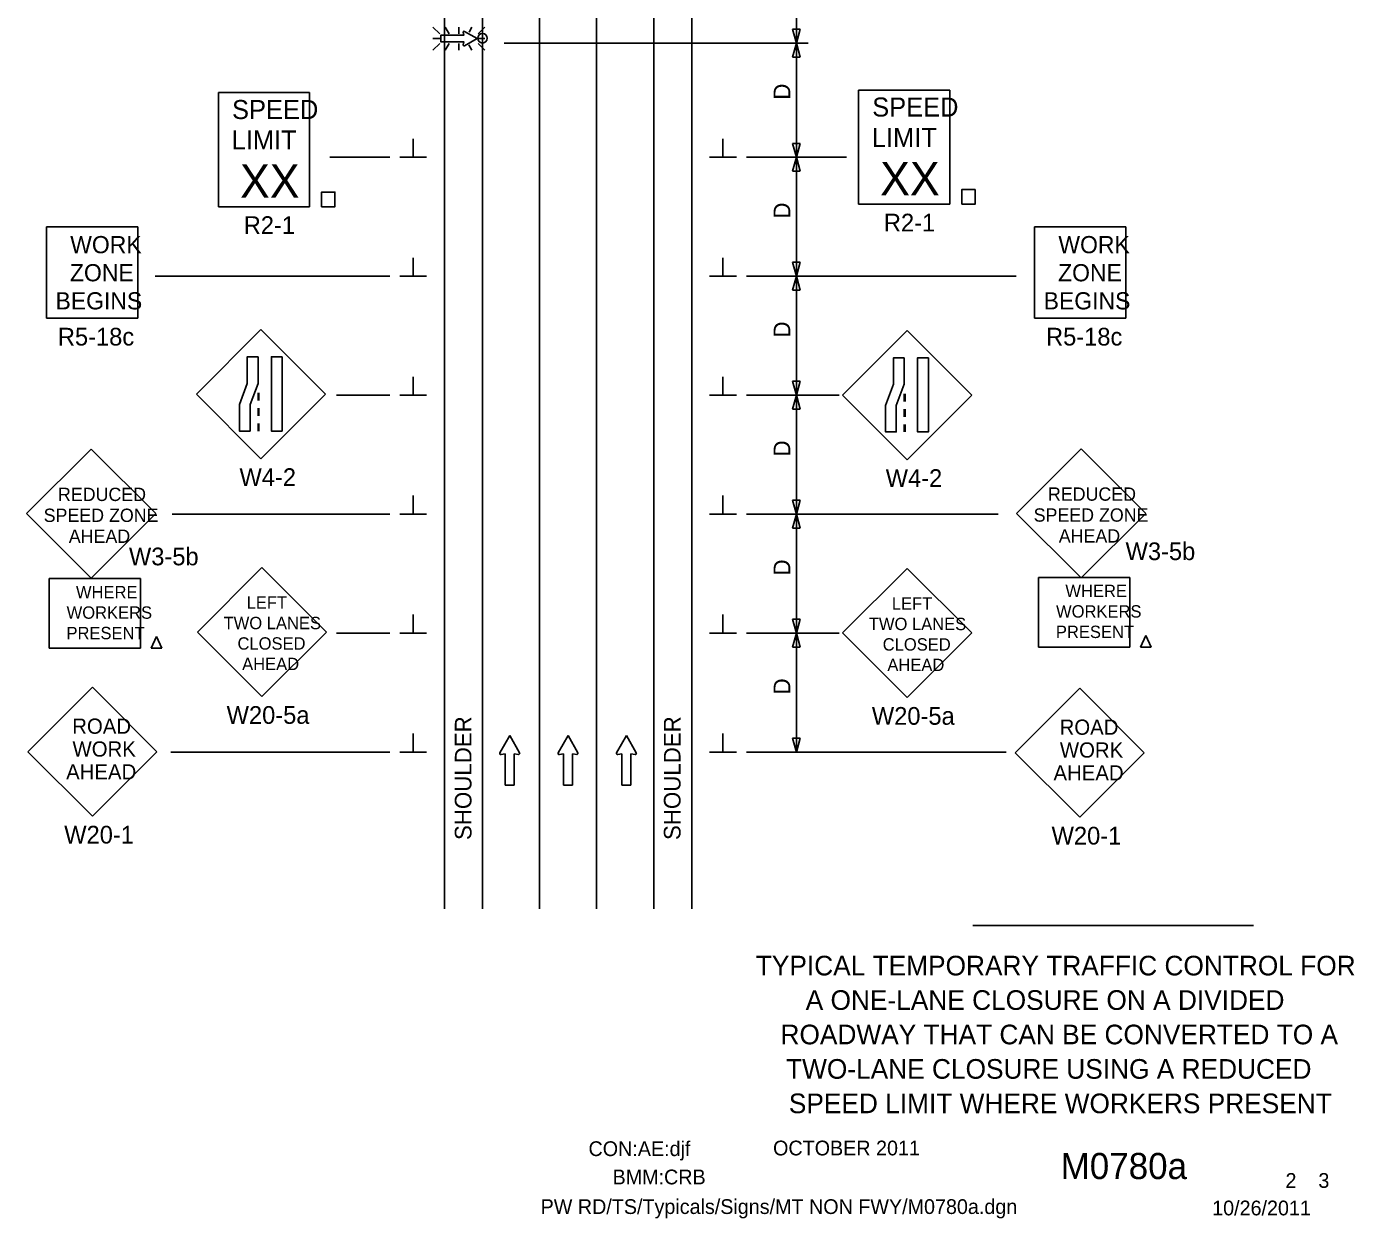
# Model space of a CAD drawing. Extents: x 16758 to 19504, y 5731 to 6944.
# Drawn here: x 17883 to 18442, y 5932 to 6433 of the extents above; entities that cross this region are included whole.
import ezdxf

# ---------------------------------------------------------------- set-up
doc = ezdxf.new("R2010")
doc.units = 0
for name, color, linetype in [('ALI_LEGAL_EX', 7, 'Continuous'), ('BORDER', 7, 'Continuous'), ('BORDER_SIGNAL_WO', 7, 'Continuous'), ('MT_SCRATCH_LEVEL_E', 7, 'Continuous'), ('PAVT_EDGE_EX', 7, 'Continuous'), ('TRAFFIC_SIGNS_PR', 7, 'Continuous'), ('TYPICAL_TEXT_DIMEN_PR', 7, 'Continuous')]:
    doc.layers.add(name, color=color, linetype=linetype)

msp = doc.modelspace()

# ---------------------------------------------------------------- linework, layer by layer
at = {"layer": 'ALI_LEGAL_EX'}
for p, q in [((18099.1, 6891.16), (18099.1, 6061.98)), ((18123.1, 6891.16), (18123.1, 6061.98)), ((18123.1, 6891.16), (18123.1, 6061.98))]:
    msp.add_line(p, q, dxfattribs=at)
for points in [[(18099.1, 6391.16), (18099.1, 6366.16)], [(18123.1, 6391.16), (18123.1, 6366.16)], [(18099.1, 6291.16), (18099.1, 6266.16)], [(18123.1, 6291.16), (18123.1, 6266.16)], [(18099.1, 6191.16), (18099.1, 6166.16)], [(18123.1, 6191.16), (18123.1, 6166.16)], [(18099.1, 6091.16), (18099.1, 6066.16)], [(18123.1, 6066.16), (18123.1, 6091.16)], [(18123.1, 6091.16), (18123.1, 6066.16)]]:
    msp.add_lwpolyline(points, dxfattribs=at)
at = {"layer": 'BORDER'}
for p, q in [((18281.35, 6055), (18399.35, 6055)), ((18318.25, 6011.25), (18318.25, 6011.25))]:
    msp.add_line(p, q, dxfattribs=at)
at = {"layer": 'MT_SCRATCH_LEVEL_E'}
for p, q in [((18086.54, 6134.8), (18082.43, 6127.56)), ((18086.54, 6134.8), (18082.43, 6127.56)), ((18090.69, 6127.56), (18086.54, 6134.8)), ((18090.69, 6127.56), (18086.54, 6134.8)), ((18111.07, 6134.8), (18106.96, 6127.56)), ((18111.07, 6134.8), (18106.96, 6127.56)), ((18115.21, 6127.56), (18111.07, 6134.8)), ((18115.21, 6127.56), (18111.07, 6134.8)), ((18135.63, 6134.8), (18131.52, 6127.56)), ((18135.63, 6134.8), (18131.52, 6127.56)), ((18139.77, 6127.56), (18135.63, 6134.8)), ((18139.77, 6127.56), (18135.63, 6134.8)), ((18082.91, 6126.88), (18084.69, 6127.19)), ((18082.91, 6126.88), (18084.69, 6127.19)), ((18084.69, 6127.19), (18084.69, 6113.93)), ((18084.69, 6127.19), (18084.69, 6113.93)), ((18088.43, 6113.93), (18088.43, 6127.19)), ((18088.43, 6127.19), (18090.21, 6126.88)), ((18088.43, 6113.93), (18088.43, 6127.19)), ((18088.43, 6127.19), (18090.21, 6126.88)), ((18107.44, 6126.88), (18109.22, 6127.19)), ((18107.44, 6126.88), (18109.22, 6127.19)), ((18109.22, 6127.19), (18109.22, 6113.93)), ((18109.22, 6127.19), (18109.22, 6113.93)), ((18112.96, 6113.93), (18112.96, 6127.19)), ((18112.96, 6127.19), (18114.73, 6126.88)), ((18112.96, 6113.93), (18112.96, 6127.19)), ((18112.96, 6127.19), (18114.73, 6126.88)), ((18132, 6126.88), (18133.77, 6127.19)), ((18132, 6126.88), (18133.77, 6127.19)), ((18133.77, 6127.19), (18133.77, 6113.93)), ((18133.77, 6127.19), (18133.77, 6113.93)), ((18137.52, 6113.93), (18137.52, 6127.19)), ((18137.52, 6127.19), (18139.29, 6126.88)), ((18137.52, 6113.93), (18137.52, 6127.19)), ((18137.52, 6127.19), (18139.29, 6126.88)), ((18084.69, 6113.93), (18088.43, 6113.93)), ((18084.69, 6113.93), (18088.43, 6113.93)), ((18109.22, 6113.93), (18112.96, 6113.93)), ((18109.22, 6113.93), (18112.96, 6113.93)), ((18133.77, 6113.93), (18137.52, 6113.93)), ((18133.77, 6113.93), (18137.52, 6113.93))]:
    msp.add_line(p, q, dxfattribs=at)
for centre, start, end in [((18082.84, 6127.33), 150.4248, 279.9638), ((18082.84, 6127.33), 150.4248, 279.9638), ((18090.28, 6127.34), 260.0362, 29.7731), ((18090.28, 6127.34), 260.0362, 29.7731), ((18107.36, 6127.33), 150.4248, 279.9638), ((18107.36, 6127.33), 150.4248, 279.9638), ((18114.8, 6127.34), 260.0362, 29.7731), ((18114.8, 6127.34), 260.0362, 29.7731), ((18131.92, 6127.33), 150.4248, 279.9638), ((18131.92, 6127.33), 150.4248, 279.9638), ((18139.36, 6127.34), 260.0362, 29.7731), ((18139.36, 6127.34), 260.0362, 29.7731)]:
    msp.add_arc(centre, 0.463, start, end, dxfattribs=at)
at = {"layer": 'PAVT_EDGE_EX'}
for p, q in [((18059.1, 6919.77), (18059.1, 6061.98)), ((18075.1, 6919.77), (18075.1, 6061.98)), ((18147.1, 6919.77), (18147.1, 6061.98)), ((18163.1, 6919.77), (18163.1, 6061.98)), ((18075.1, 6891.16), (18075.1, 6061.98))]:
    msp.add_line(p, q, dxfattribs=at)
at = {"layer": 'TRAFFIC_SIGNS_PR'}
for p, q in [((18057.12, 6429.83), (18054.3, 6432.65)), ((18059.42, 6432.65), (18061.04, 6429.83)), ((18065.2, 6429.83), (18065.2, 6432.65)), ((18070.67, 6432.65), (18069.47, 6430.56)), ((18076.11, 6432.65), (18073.29, 6429.83)), ((18057.12, 6427.8), (18054.3, 6427.8)), ((18073.29, 6427.8), (18076.11, 6427.8)), ((18057.12, 6425.77), (18054.3, 6422.94)), ((18061.07, 6425.77), (18059.44, 6422.94)), ((18065.2, 6425.77), (18065.2, 6422.94)), ((18069.39, 6425.13), (18070.65, 6422.94)), ((18076.11, 6422.95), (18073.29, 6425.77)), ((17964.04, 6405.12), (18002.44, 6405.12)), ((17964.04, 6357.12), (17964.04, 6405.12)), ((18002.44, 6357.12), (18002.44, 6405.12)), ((18233.22, 6406.17), (18271.62, 6406.17)), ((18233.22, 6358.17), (18233.22, 6406.17)), ((18271.62, 6358.17), (18271.62, 6406.17)), ((17964.04, 6357.12), (18002.44, 6357.12)), ((18233.22, 6358.17), (18271.62, 6358.17)), ((17891.76, 6310.22), (17891.76, 6348.61)), ((17891.76, 6348.61), (17930.16, 6348.61)), ((17930.16, 6310.22), (17930.16, 6348.61)), ((18307.26, 6310.22), (18307.26, 6348.61)), ((18307.26, 6348.61), (18345.66, 6348.61)), ((18345.66, 6310.22), (18345.66, 6348.61)), ((17891.76, 6310.22), (17930.16, 6310.22)), ((18307.26, 6310.22), (18345.66, 6310.22)), ((17981.97, 6305.48), (17954.82, 6278.33)), ((18009.13, 6278.33), (17981.97, 6305.48)), ((18253.69, 6305.09), (18226.54, 6277.93)), ((18280.85, 6277.93), (18253.69, 6305.09)), ((17954.82, 6278.33), (17981.97, 6251.17)), ((17980.73, 6278.82), (17980.73, 6275.62)), ((17981.13, 6278.82), (17981.13, 6275.62)), ((17981.97, 6251.17), (18009.13, 6278.33)), ((18226.54, 6277.93), (18253.69, 6250.78)), ((18252.45, 6278.43), (18252.45, 6275.23)), ((18252.85, 6278.43), (18252.85, 6275.23)), ((18253.69, 6250.78), (18280.85, 6277.93)), ((17980.73, 6272.42), (17980.73, 6269.22)), ((17981.13, 6272.42), (17981.13, 6269.22)), ((18252.45, 6272.03), (18252.45, 6268.83)), ((18252.85, 6272.03), (18252.85, 6268.83)), ((17980.73, 6266.02), (17980.73, 6262.82)), ((17981.13, 6266.02), (17981.13, 6262.82)), ((18252.45, 6265.63), (18252.45, 6262.43)), ((18252.85, 6265.63), (18252.85, 6262.43)), ((17910.55, 6255.26), (17883.4, 6228.11)), ((17937.7, 6228.11), (17910.55, 6255.26)), ((18326.82, 6255.38), (18299.67, 6228.22)), ((18353.98, 6228.22), (18326.82, 6255.38)), ((17883.4, 6228.11), (17910.55, 6200.95)), ((17910.55, 6200.95), (17937.7, 6228.11)), ((18299.67, 6228.22), (18326.82, 6201.07)), ((18326.82, 6201.07), (18353.98, 6228.22)), ((17982.39, 6205.49), (17955.24, 6178.34)), ((18009.54, 6178.34), (17982.39, 6205.49)), ((18253.69, 6205.1), (18226.54, 6177.95)), ((18280.85, 6177.95), (18253.69, 6205.1)), ((17892.86, 6200.84), (17931.26, 6200.84)), ((17892.86, 6171.52), (17892.86, 6200.84)), ((17931.26, 6171.52), (17931.26, 6200.84)), ((18308.9, 6201.33), (18347.3, 6201.33)), ((18308.9, 6172.01), (18308.9, 6201.33)), ((18347.3, 6172.01), (18347.3, 6201.33)), ((17955.24, 6178.34), (17982.39, 6151.19)), ((17982.39, 6151.19), (18009.54, 6178.34)), ((18226.54, 6177.95), (18253.69, 6150.8)), ((18253.69, 6150.8), (18280.85, 6177.95)), ((17892.86, 6171.52), (17931.26, 6171.52)), ((18308.9, 6172.01), (18347.3, 6172.01)), ((17911.07, 6155.19), (17883.92, 6128.04)), ((17938.22, 6128.04), (17911.07, 6155.19)), ((18326.24, 6154.77), (18299.08, 6127.61)), ((18353.39, 6127.61), (18326.24, 6154.77)), ((17883.92, 6128.04), (17911.07, 6100.88)), ((17911.07, 6100.88), (17938.22, 6128.04)), ((18299.08, 6127.61), (18326.24, 6100.46)), ((18326.24, 6100.46), (18353.39, 6127.61))]:
    msp.add_line(p, q, dxfattribs=at)
for points in [[(18067.03, 6430.48), (18067.26, 6429.18), (18057.54, 6429.18), (18057.54, 6426.44), (18067.26, 6426.44), (18067.03, 6425.14)], [(18067.53, 6424.78), (18072.84, 6427.8), (18067.53, 6430.84)], [(17938.01, 6176.46), (17935.77, 6171.52)], [(17935.77, 6171.52), (17938.01, 6176.46)], [(17940.25, 6171.52), (17938.01, 6176.46)], [(17938.01, 6176.46), (17940.25, 6171.52)], [(18354.05, 6176.95), (18351.81, 6172.01)], [(18351.81, 6172.01), (18354.05, 6176.95)], [(18356.29, 6172.01), (18354.05, 6176.95)], [(18354.05, 6176.95), (18356.29, 6172.01)], [(17935.77, 6171.52), (17940.25, 6171.52)], [(17940.25, 6171.52), (17935.77, 6171.52)], [(18351.81, 6172.01), (18356.29, 6172.01)], [(18356.29, 6172.01), (18351.81, 6172.01)]]:
    msp.add_lwpolyline(points, dxfattribs=at)
for points in [[(18007.46, 6357.12), (18013.05, 6357.12), (18013.05, 6363.29), (18007.46, 6363.29)], [(18276.63, 6358.17), (18282.23, 6358.17), (18282.23, 6364.34), (18276.63, 6364.34)], [(17980.73, 6294.06), (17980.73, 6282.88), (17977.38, 6274), (17977.38, 6262.82), (17972.89, 6262.82), (17972.89, 6274), (17976.23, 6282.88), (17976.23, 6294.06)], [(17990.86, 6294.06), (17990.86, 6262.82), (17986.37, 6262.82), (17986.37, 6294.06)], [(18252.45, 6293.67), (18252.45, 6282.49), (18249.1, 6273.61), (18249.1, 6262.43), (18244.61, 6262.43), (18244.61, 6273.61), (18247.95, 6282.49), (18247.95, 6293.67)], [(18262.58, 6293.67), (18262.58, 6262.43), (18258.09, 6262.43), (18258.09, 6293.67)]]:
    msp.add_lwpolyline(points, close=True, dxfattribs=at)
msp.add_circle((18075.11, 6427.93), 2, dxfattribs=at)
for centre, start, end in [((18067.37, 6430.54), 61.4833, 189.9593), ((18067.37, 6425.08), 170.7308, 298.8916)]:
    msp.add_arc(centre, 0.341, start, end, dxfattribs=at)
at = {"layer": 'TYPICAL_TEXT_DIMEN_PR'}
for p, q in [((18207.1, 6425.88), (18207.1, 6456.44)), ((18207.1, 6425.88), (18205.53, 6431.74)), ((18205.53, 6431.74), (18207.1, 6431.74)), ((18207.1, 6431.74), (18208.67, 6431.74)), ((18208.67, 6431.74), (18207.1, 6425.88)), ((18084.26, 6425.88), (18212.1, 6425.88)), ((18205.53, 6420.02), (18207.1, 6425.88)), ((18207.1, 6425.88), (18207.1, 6377.89)), ((18207.1, 6425.88), (18208.67, 6420.02)), ((18207.1, 6420.02), (18205.53, 6420.02)), ((18208.67, 6420.02), (18207.1, 6420.02)), ((18045.97, 6377.89), (18045.97, 6385.67)), ((18176.22, 6377.89), (18176.22, 6385.67)), ((18207.1, 6377.89), (18205.53, 6383.75)), ((18205.53, 6383.75), (18207.1, 6383.75)), ((18207.1, 6383.75), (18208.67, 6383.75)), ((18208.67, 6383.75), (18207.1, 6377.89)), ((18010.87, 6377.89), (18036.1, 6377.89)), ((18040.35, 6377.89), (18051.6, 6377.89)), ((18181.85, 6377.89), (18170.6, 6377.89)), ((18228.18, 6377.89), (18186.1, 6377.89)), ((18205.53, 6372.03), (18207.1, 6377.89)), ((18207.1, 6377.89), (18207.1, 6327.89)), ((18207.1, 6377.89), (18208.67, 6372.03)), ((18207.1, 6372.03), (18205.53, 6372.03)), ((18208.67, 6372.03), (18207.1, 6372.03)), ((18045.97, 6327.89), (18045.97, 6335.67)), ((18176.22, 6327.89), (18176.22, 6335.67)), ((18207.1, 6327.89), (18205.53, 6333.75)), ((18205.53, 6333.75), (18207.1, 6333.75)), ((18207.1, 6333.75), (18208.67, 6333.75)), ((18208.67, 6333.75), (18207.1, 6327.89)), ((17937.41, 6327.89), (18036.1, 6327.89)), ((18040.35, 6327.89), (18051.6, 6327.89)), ((18181.85, 6327.89), (18170.6, 6327.89)), ((18299.49, 6327.89), (18186.1, 6327.89)), ((18205.53, 6322.03), (18207.1, 6327.89)), ((18207.1, 6327.89), (18208.67, 6322.03)), ((18207.1, 6327.89), (18207.1, 6277.89)), ((18207.1, 6322.03), (18205.53, 6322.03)), ((18208.67, 6322.03), (18207.1, 6322.03)), ((18045.97, 6277.89), (18045.97, 6285.67)), ((18176.22, 6277.89), (18176.22, 6285.67)), ((18207.1, 6277.89), (18205.53, 6283.75)), ((18205.53, 6283.75), (18207.1, 6283.75)), ((18207.1, 6283.75), (18208.67, 6283.75)), ((18208.67, 6283.75), (18207.1, 6277.89)), ((18013.78, 6277.89), (18036.1, 6277.89)), ((18040.35, 6277.89), (18051.6, 6277.89)), ((18181.85, 6277.89), (18170.6, 6277.89)), ((18225.1, 6277.89), (18186.1, 6277.89)), ((18205.53, 6272.03), (18207.1, 6277.89)), ((18207.1, 6277.89), (18207.1, 6227.89)), ((18207.1, 6277.89), (18208.67, 6272.03)), ((18207.1, 6272.03), (18205.53, 6272.03)), ((18208.67, 6272.03), (18207.1, 6272.03)), ((18045.97, 6227.89), (18045.97, 6235.67)), ((18176.22, 6227.89), (18176.22, 6235.67)), ((18207.1, 6227.89), (18205.53, 6233.75)), ((18205.53, 6233.75), (18207.1, 6233.75)), ((18207.1, 6233.75), (18208.67, 6233.75)), ((18208.67, 6233.75), (18207.1, 6227.89)), ((17944.69, 6227.89), (18036.1, 6227.89)), ((18040.35, 6227.89), (18051.6, 6227.89)), ((18181.85, 6227.89), (18170.6, 6227.89)), ((18291.89, 6227.89), (18186.1, 6227.89)), ((18205.53, 6222.03), (18207.1, 6227.89)), ((18207.1, 6227.89), (18207.1, 6177.89)), ((18207.1, 6227.89), (18208.67, 6222.03)), ((18207.1, 6222.03), (18205.53, 6222.03)), ((18208.67, 6222.03), (18207.1, 6222.03)), ((18045.97, 6177.89), (18045.97, 6185.67)), ((18176.22, 6177.89), (18176.22, 6185.67)), ((18207.1, 6177.89), (18205.53, 6183.75)), ((18205.53, 6183.75), (18207.1, 6183.75)), ((18207.1, 6183.75), (18208.67, 6183.75)), ((18208.67, 6183.75), (18207.1, 6177.89)), ((18013.78, 6177.89), (18036.1, 6177.89)), ((18040.35, 6177.89), (18051.6, 6177.89)), ((18181.85, 6177.89), (18170.6, 6177.89)), ((18225.1, 6177.89), (18186.1, 6177.89)), ((18205.53, 6172.03), (18207.1, 6177.89)), ((18207.1, 6177.89), (18207.1, 6127.89)), ((18207.1, 6177.89), (18208.67, 6172.03)), ((18207.1, 6172.03), (18205.53, 6172.03)), ((18208.67, 6172.03), (18207.1, 6172.03)), ((18045.97, 6127.89), (18045.97, 6135.67)), ((18176.22, 6127.89), (18176.22, 6135.67)), ((18207.1, 6127.89), (18205.53, 6133.75)), ((18205.53, 6133.75), (18207.1, 6133.75)), ((18207.1, 6133.75), (18208.67, 6133.75)), ((18208.67, 6133.75), (18207.1, 6127.89)), ((17944, 6127.89), (18036.1, 6127.89)), ((18040.35, 6127.89), (18051.6, 6127.89)), ((18181.85, 6127.89), (18170.6, 6127.89)), ((18295.32, 6127.89), (18186.1, 6127.89))]:
    msp.add_line(p, q, dxfattribs=at)

# ---------------------------------------------------------------- texts
at = {"layer": 'BORDER'}
for s, p in [('TYPICAL TEMPORARY TRAFFIC CONTROL FOR', (18190.04, 6033.99)), ('A ONE-LANE CLOSURE ON A DIVIDED', (18211.02, 6019.51)), ('ROADWAY THAT CAN BE CONVERTED TO A', (18200.42, 6005.04)), ('TWO-LANE CLOSURE USING A REDUCED ', (18202.75, 5990.56)), ('SPEED LIMIT WHERE WORKERS PRESENT', (18203.92, 5976.08))]:
    msp.add_text(s, height=8.2598, dxfattribs=at).set_placement(p)
at = {"layer": 'BORDER_SIGNAL_WO'}
for s, height, p in [('CON:AE:djf', 6.2, (18119.69, 5958.06)), ('    OCTOBER 2011    ', 6.2, (18188.08, 5958.34)), ('    M0780a   ', 11, (18301.86, 5948.38)), ('BMM:CRB   ', 6.2, (18129.81, 5946.17)), (' 2    3 ', 6.2, (18410.45, 5944.7)), ('PW RD/TS/Typicals/Signs/MT NON FWY/M0780a.dgn    ', 6.2, (18099.55, 5933.71)), ('10/26/2011    ', 6.2, (18381.93, 5933.13))]:
    msp.add_text(s, height=height, dxfattribs=at).set_placement(p)
at = {"layer": 'TRAFFIC_SIGNS_PR'}
for s, height, p in [('SPEED', 8, (17969.81, 6393.98)), ('SPEED', 8, (18238.98, 6395.03)), ('LIMIT', 8, (17969.65, 6381.18)), ('LIMIT', 8, (18238.82, 6382.23)), ('XX', 14.031, (17973.15, 6360.88)), ('XX', 14.031, (18242.33, 6361.93)), ('R2-1', 7.44, (18243.89, 6346.73)), ('R2-1', 7.44, (17974.72, 6345.68)), ('WORK', 7.217, (17901.76, 6337.58)), ('WORK', 7.217, (18317.26, 6337.58)), ('ZONE', 7.217, (17901.64, 6325.77)), ('ZONE', 7.217, (18317.14, 6325.77)), ('BEGINS', 7.217, (17895.57, 6313.96)), ('BEGINS', 7.217, (18311.07, 6313.96)), ('R5-18c', 7.44, (17896.57, 6298.78)), ('R5-18c', 7.44, (18312.07, 6298.78)), ('W4-2', 7.44, (17972.93, 6239.73)), ('W4-2', 7.44, (18244.65, 6239.34)), ('REDUCED', 5.6, (17896.61, 6233.41)), ('REDUCED', 5.6, (18312.88, 6233.53)), ('SPEED ZONE', 5.6, (17890.6, 6224.61)), ('SPEED ZONE', 5.6, (18306.87, 6224.73)), ('AHEAD', 5.6, (17901.16, 6215.82)), ('AHEAD', 5.6, (18317.43, 6215.93)), ('W3-5b', 7.44, (18345.52, 6208.57)), ('W3-5b', 7.44, (17926.45, 6206.39)), ('WHERE', 5.2, (17904.17, 6192.52)), ('WHERE', 5.2, (18320.21, 6193.02)), ('LEFT', 5.2, (17975.93, 6188.13)), ('LEFT', 5.2, (18247.23, 6187.74)), ('WORKERS', 5.2, (17900.25, 6183.92)), ('WORKERS', 5.2, (18316.28, 6184.42)), ('TWO LANES', 5.2, (17966.25, 6179.53)), ('TWO LANES', 5.2, (18237.55, 6179.14)), ('PRESENT', 5.2, (18316.22, 6175.82)), ('PRESENT', 5.2, (17900.18, 6175.32)), ('CLOSED', 5.2, (17972.1, 6170.93)), ('CLOSED', 5.2, (18243.4, 6170.54)), ('AHEAD', 5.2, (17974.05, 6162.33)), ('AHEAD', 5.2, (18245.35, 6161.94)), ('ROAD', 6.4, (17902.61, 6135.57)), ('W20-5a', 7.44, (17967.53, 6139.75)), ('W20-5a', 7.44, (18238.83, 6139.36)), ('ROAD', 6.4, (18317.78, 6135.15)), ('WORK', 6.4, (17902.72, 6125.97)), ('WORK', 6.4, (18317.89, 6125.55)), ('AHEAD', 6.4, (17900.03, 6116.37)), ('AHEAD', 6.4, (18315.2, 6115.95)), ('W20-1', 7.44, (17899.24, 6089.44)), ('W20-1', 7.44, (18314.41, 6089.02))]:
    msp.add_text(s, height=height, dxfattribs=at).set_placement(p)
at = {"layer": 'TYPICAL_TEXT_DIMEN_PR'}
for s, p in [('D', (18204.54, 6402.11)), ('D', (18204.54, 6352.11)), ('D', (18204.54, 6302.11)), ('D', (18204.54, 6252.11)), ('D', (18204.54, 6202.11)), ('D', (18204.54, 6152.11)), ('SHOULDER', (18070.48, 6090.91)), ('SHOULDER', (18158.38, 6090.91))]:
    msp.add_text(s, height=7, rotation=90, dxfattribs=at).set_placement(p)

doc.saveas('drawing.dxf')
